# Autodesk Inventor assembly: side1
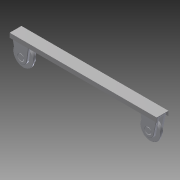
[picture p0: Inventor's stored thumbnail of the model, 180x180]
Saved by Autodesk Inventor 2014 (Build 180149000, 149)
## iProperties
Created: 2009-11
Part Number: side1
Document SubType Name: Assembly
Designer: pokornp
Mass: 81675.3 g
Surface Area: 27453 cm^2
Volume: 26478.2 cm^3
Density: 3.08462 g/cm^3
_SolveAssemblyDoc: Frame Generator Solve Assembly
_Version: 15.0.0
Author: pokornp
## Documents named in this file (6)
- C:\Users\iTools\Desktop\tutorial files\Frame Analysis 1\side1.iam
- C:\Users\iTools\Desktop\tutorial files\Frame Analysis 1\Part3.ipt
- C:\Users\iTools\Desktop\tutorial files\Frame Analysis 1\side1\Frame\Frame0001.iam
- C:\Users\iTools\Desktop\tutorial files\Frame Analysis 1\shape.ipt
- C:\Users\iTools\Desktop\tutorial files\Frame Analysis 1\wheel.ipt
- C:\Users\iTools\Desktop\tutorial files\Frame Analysis 1\axis1.ipt
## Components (8 placed, 5 different names)
1. Part3:1
2. Frame0001:1 [sub-assembly] — Mate:7, Flush:3, Mate:9, Flush:4, Mate:10, Mate:11
3. shape:1 — Mate:1, Flush:1, Mate:3, Mate:9, Flush:4, Mate:10
4. shape:2 — Mate:4, Flush:2, Mate:6, Mate:7, Flush:3, Mate:11
5. wheel:1 — Mate:2, Mate:3
6. wheel:2 — Mate:5, Mate:6
7. axis1:1 — Mate:1, Flush:1, Mate:2
8. axis1:2 — Mate:4, Flush:2, Mate:5
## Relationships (14: Mate 10, Flush 4)
- Mate:1: shape:1 ↔ axis1:1
- Flush:1: shape:1 ↔ axis1:1
- Mate:2: wheel:1 ↔ axis1:1
- Mate:3: shape:1 ↔ wheel:1
- Mate:4: shape:2 ↔ axis1:2
- Flush:2: shape:2 ↔ axis1:2
- Mate:5: wheel:2 ↔ axis1:2
- Mate:6: shape:2 ↔ wheel:2
- Mate:7: Frame0001:1 ↔ shape:2
- Flush:3: Frame0001:1 ↔ shape:2
- Mate:9: Frame0001:1 ↔ shape:1
- Flush:4: Frame0001:1 ↔ shape:1
- Mate:10: Frame0001:1 ↔ shape:1
- Mate:11: Frame0001:1 ↔ shape:2
